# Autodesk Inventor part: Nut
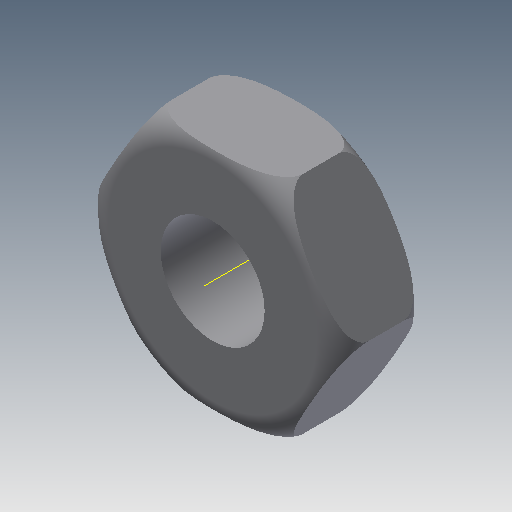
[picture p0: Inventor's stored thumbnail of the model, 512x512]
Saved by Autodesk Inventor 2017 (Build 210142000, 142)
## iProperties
Created: 2009-04
Part Number: Nut
Document SubType Name: Modeling
Designer: Sham
Density: 1 g/cm^3
Material: Generic
Appearance: Default
Author: Sham
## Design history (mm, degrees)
sketch "Sketch1"
  geometry: L1 (7.5, 12.99)-(15, 0); L2 (15, 0)-(7.5, -12.99); L3 (7.5, -12.99)-(-7.5, -12.99); L4 (-7.5, -12.99)-(-15, 0); L5 (-15, 0)-(-7.5, 12.99); L6 (-7.5, 12.99)-(7.5, 12.99); C1 r 6 at (0, 0); 1 further point
  constraints: 12 end point, 1 centre point, 1 coincident, 13 other
  dimensions: "d0" = 30 distance of L1.end L4.end; "d1" = 12 diameter of C1
extrude "Extrusion1" new body sketch "Sketch1" distance "d2" = 12; taper "d3" = 0 deg
sketch "Sketch2"
  geometry: L1 (-12, 0)-(-12, -0.022); L2 (-15, 7)-(-15, 3); L3 (0, -2.87)-(0, 12.87) reference; A1 r 3 centre (-12, 7) between (-12, 10) and (-15, 7); A2 r 3 centre (-12, 3) between (-15, 3) and (-12, 0)
  constraints: 4 end point, 4 point on circle, 2 centre point, 1 tangent
revolve "Revolution1" sketch "Sketch2" stored, may be unused: angle "d7" = 90 deg
body "Solid1"
other parameters: "d6" = 90 deg
